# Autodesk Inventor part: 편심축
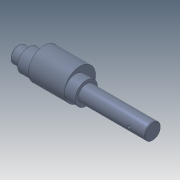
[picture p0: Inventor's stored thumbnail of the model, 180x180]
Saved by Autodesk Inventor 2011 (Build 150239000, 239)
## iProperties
Manager: 한국ATC센터
Company: 한국ATC센터
Created: 2014-07
Part Number: 편심축
Document SubType Name: Modeling
Designer: KYOUNG IL JANG
Density: 7.86 g/cm^3
Material: 강, 연강
Mass: 1544.74 g
Surface Area: 256.354 cm^2
Volume: 196.531 cm^3
Author: KYOUNG IL JANG
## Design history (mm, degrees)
sketch "스케치1"
  geometry: L1 (-105, 0)-(105, 0); L2 (-105, 0)-(-105, 12.5); L3 (-105, 12.5)-(-89, 12.5); L4 (-89, 12.5)-(-89, 17.5); L5 (-89, 17.5)-(-82, 17.5); L6 (-82, 17.5)-(-82, 12.5); L7 (-82, 12.5)-(-0.35, 12.5); L8 (-0.35, 12.5)-(-0.35, 11.95); L9 (-0.35, 11.95)-(1, 11.95); L10 (1, 11.95)-(1, 12.5); L11 (1, 12.5)-(105, 12.5); L12 (105, 12.5)-(105, 0); L13 (70, 12.5)-(70, 9.1); L14 (70, 9.1)-(95, 9.1); L15 (95, 9.1)-(95, 12.5); L16 (80, -12.5)-(82.5, -12.5); L17 (82.5, -12.5)-(80, -10); L18 (80, -10)-(80, -12.5); L19 (1, 12.5)-(-0.35, 12.5); 2 further points
  constraints: 38 end point, 8 parallel, 5 collinear, 5 perpendicular, 2 point on line, 1 coincident, 1 horizontal, 1 midpoint, 1 vertical
  dimensions: "d0" = 210 distance of L1.start L1.end; "d1" = 25 diameter of L3 L1; "d2" = 35 diameter of L5 L1; "d3" = 16 distance of L2.end L3.end; "d6" = 1.35 distance of L8.end L9.end; "d7" = 23.9 diameter of L9 L1; "d8" = 3.4 distance between parallel lines of L14 L11; "d9" = 10 distance between parallel lines of L15 L12; "d10" = 25 distance of L13.end L14.end; "d11" = 25 diameter of L16 L1 (= d1); "d12" = 25 distance from line of L12 L16.start; "d13" = 45 deg angle of L17 L18; "d14" = 5 diameter of L16.end L18; "d27" = 104 distance between parallel lines of L10 L12; "d35" = 7 distance of L4.end L5.end
revolve "회전1" stored, may be unused: angle "d15" = 90 deg
revolve "회전2" stored, may be unused: angle "d16" = 90 deg
extrude "돌출1" cut sketch "스케치1" stored distance "d17" = 8; taper "d18" = 0 deg
fillet "모깎기1" dims "d19" = 4
node "작업 평면1"
sketch "스케치2"
  geometry: C1 r 12.5 at (0, 0) reference; C2 r 17.5 at (0, 0); C3 r 24.5 at (0, 7); 1 further point
  constraints: 2 centre point, 1 coincident, 1 tangent, 1 vertical alignment
  dimensions: "d32" = 35 diameter of C2; "d33" = 49 diameter of C3 (derived); "d34" = 7 distance of C3.centre point (0, 0)
extrude "돌출2" join sketch "스케치2" distance "d22" = 56; taper "d23" = 0 deg
chamfer "모따기1" distance "d24" = 1; stored, may be unused: second distance "d25" = 2, angle "d26" = 45 deg
feature "면 이동1" dims "d31" = 83
node "솔리드1"
